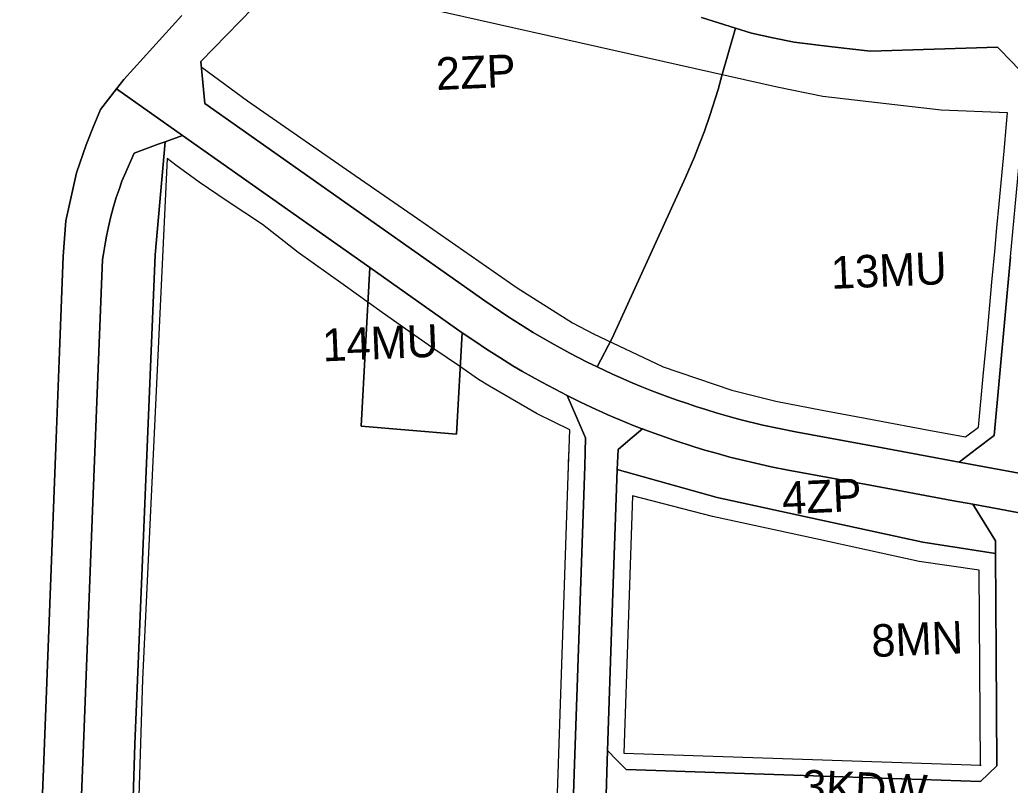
# Model space of a CAD drawing. Extents: x 7418021 to 7419743, y 5540231 to 5541685.
# Drawn here: x 7418764.3 to 7419069.1, y 5540790.3 to 5541025.9 of the extents above; entities that cross this region are included whole.
import ezdxf

# ---------------------------------------------------------------- set-up
doc = ezdxf.new("R2010")
doc.units = 0
for name, color, linetype in [('linie_rozgraniczajace', 7, 'Continuous'), ('linie_zabudowy_nieprzekraczalne', 7, 'Continuous'), ('oznaczenia_przeznaczen', 7, 'Continuous')]:
    doc.layers.add(name, color=color, linetype=linetype)

msp = doc.modelspace()

# ---------------------------------------------------------------- linework, layer by layer
at = {"layer": 'linie_rozgraniczajace'}
for points in [[(7418860.04, 5541054.22), (7418820.04, 5541013.07), (7418821.25, 5541000.14), (7418864.33, 5540969.75), (7418907.41, 5540939.37), (7418914.5, 5540934.56), (7418922.26, 5540929.7), (7418927.85, 5540926.44), (7418933.51, 5540923.34), (7418938.91, 5540920.56), (7418941.93, 5540919.08), (7418944.34, 5540917.95), (7418946.64, 5540916.87), (7418948.38, 5540916.09), (7418952.74, 5540914.19), (7418955.73, 5540912.95), (7418958.77, 5540911.74), (7418963.71, 5540909.89), (7418966.59, 5540908.83), (7418969.44, 5540907.87), (7418972.29, 5540906.9), (7418975.41, 5540905.94), (7418978.54, 5540904.97), (7418982.2, 5540903.95), (7418985.87, 5540902.93), (7418992.99, 5540901.18), (7419002.97, 5540899.12), (7419028.15, 5540894.45), (7419053.34, 5540889.78), (7419082.87, 5540884.31)], [(7418974.12, 5541026.58), (7418984.55, 5541023.35), (7418982.41, 5541015.88), (7418980.26, 5541008.4), (7418979.16, 5541004.46), (7418976.63, 5540996.45), (7418975.02, 5540991.65), (7418973.49, 5540987.7), (7418971.96, 5540983.76), (7418969.17, 5540977.35), (7418957.88, 5540952.64), (7418946.59, 5540927.93), (7418941.93, 5540919.08), (7418938.91, 5540920.56), (7418933.51, 5540923.34), (7418927.85, 5540926.44), (7418922.26, 5540929.7), (7418914.5, 5540934.56), (7418907.41, 5540939.37), (7418864.33, 5540969.75), (7418821.25, 5541000.14), (7418820.04, 5541013.07), (7418860.04, 5541054.22)], [(7418814.14, 5541027.22), (7418796.31, 5541007.56), (7418794.05, 5541004.64), (7418789.12, 5540998.29), (7418786.91, 5540992.85), (7418784.7, 5540987.42), (7418781.71, 5540978.85), (7418780.09, 5540971.46), (7418778.47, 5540964.06), (7418777.62, 5540953.12), (7418776.5, 5540923.73), (7418775.38, 5540894.35), (7418773.52, 5540846.17), (7418771.67, 5540797.99), (7418770.78, 5540775.04), (7418769.55, 5540743.2), (7418769.21, 5540734.31), (7418767.27, 5540685.15), (7418766.02, 5540652.51), (7418764.77, 5540619.88), (7418764.16, 5540602.99)], [(7419079.41, 5540872.75), (7419065.92, 5540875.25), (7419057.59, 5540876.79), (7419051.15, 5540877.98), (7419025.97, 5540882.65), (7419000.79, 5540887.32), (7418995.47, 5540888.36), (7418982.83, 5540891.32), (7418978.99, 5540892.39), (7418975.15, 5540893.45), (7418971.87, 5540894.47), (7418965.59, 5540896.5), (7418956.6, 5540899.72), (7418955.89, 5540899.99), (7418955.49, 5540900.14), (7418952.8, 5540901.2), (7418948.9, 5540902.79), (7418947.24, 5540903.49), (7418945.3, 5540904.33), (7418943.48, 5540905.14), (7418941.65, 5540905.96), (7418936.85, 5540908.2), (7418935.19, 5540909.02), (7418932.73, 5540910.25), (7418924.91, 5540914.37), (7418921.94, 5540915.99), (7418919, 5540917.71), (7418916.05, 5540919.43), (7418912, 5540921.97), (7418907.94, 5540924.51), (7418904.31, 5540926.98), (7418900.47, 5540929.59), (7418872.05, 5540949.63), (7418857.42, 5540959.95), (7418814.33, 5540990.33), (7418794.05, 5541004.64), (7418796.31, 5541007.56), (7418814.14, 5541027.22)], [(7419373.79, 5541027.27), (7419234.54, 5541023), (7419095.29, 5541018.74), (7419084.37, 5541008.48), (7419080.29, 5540964.41), (7419078.72, 5540947.43), (7419073.96, 5540896.09), (7419078.43, 5540890.2), (7419082.87, 5540884.31), (7419053.34, 5540889.78), (7419058.73, 5540893.85), (7419064.09, 5540897.92), (7419069.18, 5540952.92), (7419074.28, 5541007.93), (7419069.74, 5541012.72), (7419065.21, 5541017.52), (7419045.63, 5541016.89), (7419026.05, 5541016.25), (7419014.29, 5541017.62), (7419002.54, 5541018.98), (7418996.01, 5541020.4), (7418989.47, 5541021.83), (7418984.55, 5541023.35), (7418974.12, 5541026.58)], [(7419069.18, 5540952.92), (7419064.09, 5540897.92), (7419058.73, 5540893.85), (7419053.34, 5540889.78), (7419028.15, 5540894.45), (7419002.97, 5540899.12), (7418992.99, 5540901.18), (7418985.87, 5540902.93), (7418982.2, 5540903.95), (7418978.54, 5540904.97), (7418975.41, 5540905.94), (7418972.29, 5540906.9), (7418969.44, 5540907.87), (7418966.59, 5540908.83), (7418963.71, 5540909.89), (7418958.77, 5540911.74), (7418955.73, 5540912.95), (7418952.74, 5540914.19), (7418948.38, 5540916.09), (7418946.64, 5540916.87), (7418944.34, 5540917.95), (7418941.93, 5540919.08), (7418946.59, 5540927.93), (7418957.88, 5540952.64), (7418969.17, 5540977.35), (7418971.96, 5540983.76), (7418973.49, 5540987.7), (7418975.02, 5540991.65), (7418976.63, 5540996.45), (7418979.16, 5541004.46), (7418980.26, 5541008.4), (7418982.41, 5541015.88), (7418984.55, 5541023.35), (7418989.47, 5541021.83), (7418996.01, 5541020.4), (7419002.54, 5541018.98), (7419014.29, 5541017.62), (7419026.05, 5541016.25), (7419045.63, 5541016.89), (7419065.21, 5541017.52), (7419069.74, 5541012.72)], [(7418770.78, 5540775.04), (7418771.67, 5540797.99), (7418773.52, 5540846.17), (7418775.38, 5540894.35), (7418776.5, 5540923.73), (7418777.62, 5540953.12), (7418778.47, 5540964.06), (7418780.09, 5540971.46), (7418781.71, 5540978.85), (7418784.7, 5540987.42), (7418786.91, 5540992.85), (7418789.12, 5540998.29), (7418794.05, 5541004.64)], [(7418794.05, 5541004.64), (7418814.33, 5540990.33), (7418809, 5540988.38), (7418806.91, 5540987.61), (7418799.48, 5540984.89), (7418796.48, 5540978.12), (7418795.72, 5540976.24), (7418794.84, 5540973.71), (7418793.96, 5540971.19), (7418793.08, 5540968.09), (7418792.2, 5540964.99), (7418791.58, 5540962.15), (7418790.96, 5540959.31), (7418790.67, 5540957.53), (7418790.38, 5540955.75), (7418790.05, 5540953.92), (7418789.71, 5540952.09), (7418786.69, 5540874.81), (7418783.66, 5540797.53), (7418781.89, 5540751.62)], [(7418781.89, 5540751.62), (7418783.66, 5540797.53), (7418786.69, 5540874.81), (7418789.71, 5540952.09), (7418790.05, 5540953.92), (7418790.38, 5540955.75), (7418790.67, 5540957.53), (7418790.96, 5540959.31), (7418791.58, 5540962.15), (7418792.2, 5540964.99), (7418793.08, 5540968.09), (7418793.96, 5540971.19), (7418794.84, 5540973.71), (7418795.72, 5540976.24), (7418796.48, 5540978.12), (7418799.48, 5540984.89), (7418806.91, 5540987.61), (7418809, 5540988.38), (7418806.01, 5540953.6), (7418799.68, 5540802.96), (7418797.25, 5540723.86)], [(7418797.25, 5540723.86), (7418799.68, 5540802.96), (7418806.01, 5540953.6), (7418809, 5540988.38), (7418814.33, 5540990.33), (7418857.42, 5540959.95), (7418872.05, 5540949.63), (7418870.68, 5540925.22), (7418869.32, 5540900.81), (7418884.02, 5540899.61), (7418898.73, 5540898.4), (7418900.47, 5540929.59), (7418904.31, 5540926.98), (7418907.94, 5540924.51), (7418912, 5540921.97), (7418916.05, 5540919.43), (7418919, 5540917.71), (7418921.94, 5540915.99), (7418924.91, 5540914.37), (7418932.73, 5540910.25), (7418938.4, 5540897.24), (7418938.26, 5540892.88), (7418938.13, 5540888.51), (7418936.53, 5540841.15), (7418934.93, 5540793.8), (7418933.44, 5540749.87)], [(7418933.44, 5540749.87), (7418934.93, 5540793.8), (7418936.53, 5540841.15), (7418938.13, 5540888.51), (7418938.26, 5540892.88), (7418938.4, 5540897.24), (7418932.73, 5540910.25), (7418935.19, 5540909.02), (7418936.85, 5540908.2), (7418941.65, 5540905.96), (7418943.48, 5540905.14), (7418945.3, 5540904.33), (7418947.24, 5540903.49), (7418948.9, 5540902.79), (7418952.8, 5540901.2), (7418955.49, 5540900.14), (7418955.89, 5540899.99), (7418952.14, 5540896.84), (7418948.39, 5540893.7), (7418948.1, 5540887.48), (7418946.52, 5540840.65), (7418945.18, 5540800.98), (7418944.6, 5540783.96)], [(7418944.6, 5540783.96), (7418945.18, 5540800.98), (7418948.04, 5540798.07), (7418950.91, 5540795.16), (7419005.44, 5540793.33), (7419059.97, 5540791.51), (7419064.94, 5540796.34), (7419064.72, 5540830.92), (7419064.52, 5540861.7), (7419064.5, 5540865.5), (7419061.04, 5540871.15), (7419057.59, 5540876.79)], [(7419057.59, 5540876.79), (7419065.92, 5540875.25), (7419079.41, 5540872.75)]]:
    msp.add_lwpolyline(points, dxfattribs=at)
for points in [[(7418872.05, 5540949.63), (7418900.47, 5540929.59), (7418898.73, 5540898.4), (7418884.02, 5540899.61), (7418869.32, 5540900.81), (7418870.68, 5540925.22)], [(7418955.89, 5540899.99), (7418956.6, 5540899.72), (7418965.59, 5540896.5), (7418971.87, 5540894.47), (7418975.15, 5540893.45), (7418978.99, 5540892.39), (7418982.83, 5540891.32), (7418995.47, 5540888.36), (7419000.79, 5540887.32), (7419025.97, 5540882.65), (7419051.15, 5540877.98), (7419057.59, 5540876.79), (7419061.04, 5540871.15), (7419064.5, 5540865.5), (7419064.52, 5540861.7), (7419053.33, 5540863.4), (7419042.14, 5540865.11), (7419010.52, 5540872.01), (7418978.9, 5540878.91), (7418963.5, 5540883.19), (7418948.1, 5540887.48), (7418948.39, 5540893.7), (7418952.14, 5540896.84)], [(7418948.1, 5540887.48), (7418963.5, 5540883.19), (7418978.9, 5540878.91), (7419010.52, 5540872.01), (7419042.14, 5540865.11), (7419053.33, 5540863.4), (7419064.52, 5540861.7), (7419064.72, 5540830.92), (7419064.94, 5540796.34), (7419059.97, 5540791.51), (7419005.44, 5540793.33), (7418950.91, 5540795.16), (7418948.04, 5540798.07), (7418945.18, 5540800.98), (7418946.52, 5540840.65)]]:
    msp.add_lwpolyline(points, close=True, dxfattribs=at)
at = {"layer": 'linie_zabudowy_nieprzekraczalne'}
for points in [[(7418997.35, 5541005.22), (7418845.61, 5541039.37)], [(7418820.44, 5541011.26), (7418834.38, 5541001)], [(7419011.42, 5541002.33), (7418997.35, 5541005.22)], [(7418834.38, 5541001), (7418866.17, 5540978.96)], [(7419028.22, 5541000.34), (7419011.42, 5541002.33)], [(7419047.86, 5540998.1), (7419028.22, 5541000.34)], [(7419068.28, 5540997.32), (7419047.86, 5540998.1)], [(7419067.96, 5540993.92), (7419068.28, 5540997.32)], [(7419067.18, 5540985.43), (7419067.96, 5540993.92)], [(7419065.68, 5540969.29), (7419067.18, 5540985.43)], [(7418809.63, 5540983.24), (7418802.06, 5540822.84)], [(7418812.28, 5540981.19), (7418809.63, 5540983.24)], [(7418819.55, 5540975.91), (7418812.28, 5540981.19)], [(7418866.17, 5540978.96), (7418886.66, 5540964.75)], [(7418828.07, 5540970.1), (7418819.55, 5540975.91)], [(7418839.04, 5540962.86), (7418828.07, 5540970.1)], [(7419065, 5540961.91), (7419065.68, 5540969.29)], [(7418886.66, 5540964.75), (7418917.39, 5540943.44)], [(7418849.98, 5540954.28), (7418839.04, 5540962.86)], [(7419064.33, 5540954.65), (7419065, 5540961.91)], [(7418863.83, 5540944.4), (7418849.98, 5540954.28)], [(7419063.45, 5540945.16), (7419064.33, 5540954.65)], [(7418875.86, 5540935.86), (7418863.83, 5540944.4)], [(7418917.39, 5540943.44), (7418934.42, 5540932.65)], [(7419062.14, 5540931.02), (7419063.45, 5540945.16)], [(7418884.87, 5540929.45), (7418875.86, 5540935.86)], [(7418934.42, 5540932.65), (7418940.81, 5540929.31)], [(7419061.55, 5540924.68), (7419062.14, 5540931.02)], [(7418892.04, 5540924.48), (7418884.87, 5540929.45)], [(7418940.6, 5540929.42), (7418940.81, 5540929.31)], [(7418940.81, 5540929.31), (7418962.03, 5540919.21)], [(7418899.58, 5540919.26), (7418892.04, 5540924.48)], [(7419060.77, 5540916.23), (7419061.55, 5540924.68)], [(7418905.43, 5540915.24), (7418899.58, 5540919.26)], [(7418961.98, 5540919.23), (7418983.4, 5540911.92)], [(7418908.85, 5540913.18), (7418905.43, 5540915.24)], [(7419059.32, 5540900.58), (7419060.77, 5540916.23)], [(7418923.49, 5540904.65), (7418908.85, 5540913.18)], [(7418983.4, 5540911.92), (7418996.95, 5540908.51)], [(7418996.95, 5540908.51), (7419011.22, 5540905.73)], [(7418933.54, 5540899.71), (7418923.49, 5540904.65)], [(7419011.22, 5540905.73), (7419026.08, 5540902.97)], [(7419026.08, 5540902.97), (7419045.67, 5540899.34)], [(7419055.32, 5540897.55), (7419059.32, 5540900.58)], [(7418932.93, 5540882.66), (7418933.54, 5540899.71)], [(7419045.67, 5540899.34), (7419055.32, 5540897.55)], [(7418933.14, 5540888.68), (7418933.27, 5540892.7)], [(7418929.93, 5540793.97), (7418933.14, 5540888.68)], [(7418952.83, 5540879.37), (7418950.15, 5540800.19)], [(7418977.46, 5540873.08), (7418952.83, 5540879.37)], [(7419009.26, 5540866.14), (7418977.46, 5540873.08)], [(7419041.05, 5540859.21), (7419009.26, 5540866.14)], [(7419059.56, 5540856.48), (7419041.05, 5540859.21)], [(7419059.94, 5540796.31), (7419059.56, 5540856.48)], [(7418802.06, 5540822.84), (7418795.06, 5540600.62)], [(7418950.15, 5540800.19), (7419060.14, 5540796.51)], [(7418926.96, 5540706.11), (7418929.93, 5540793.97)]]:
    msp.add_lwpolyline(points, dxfattribs=at)

# ---------------------------------------------------------------- texts
at = {"layer": 'oznaczenia_przeznaczen'}
for s, rotation, p in [('2ZP', 2.5711, (7418892.59, 5541004.28)), ('13MU', 2.4191, (7419014.09, 5540943.08)), ('14MU', 2.396, (7418857.6, 5540920.76)), ('4ZP', 2.5711, (7418999.07, 5540873.7)), ('8MN', 2.4191, (7419026.53, 5540829.76)), ('3KDW', 357.5522, (7419004.76, 5540785.15))]:
    msp.add_text(s, height=10, rotation=rotation, dxfattribs=at).set_placement(p)

doc.saveas('drawing.dxf')
